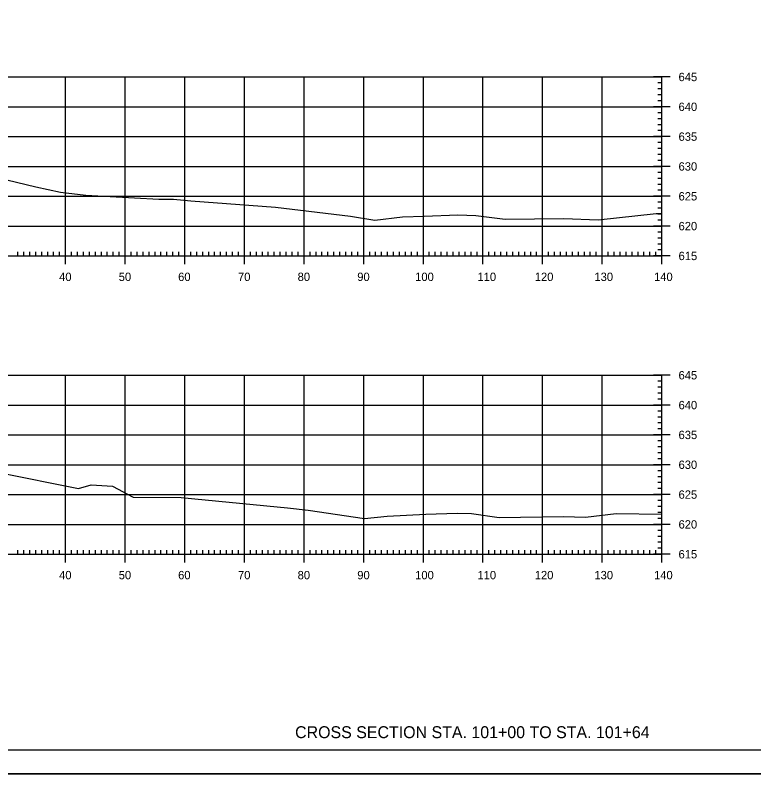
# Model space of a CAD drawing. Extents: x 1381471 to 1382703, y 370300 to 371487.
# Drawn here: x 1382168.2 to 1382292, y 370420.5 to 370547.6 of the extents above; entities that cross this region are included whole.
import ezdxf

# ---------------------------------------------------------------- set-up
doc = ezdxf.new("R2010")
doc.units = 0
doc.layers.add('Level 45', color=7, linetype='Continuous')

msp = doc.modelspace()

# ---------------------------------------------------------------- linework, layer by layer
at = {"layer": 'Level 45'}
for p, q in [((1381996.61, 370537.27), (1382276.61, 370537.27)), ((1382176.61, 370507.27), (1382176.61, 370537.27)), ((1382186.61, 370507.27), (1382186.61, 370537.27)), ((1382196.61, 370507.27), (1382196.61, 370537.27)), ((1382206.61, 370507.27), (1382206.61, 370537.27)), ((1382216.61, 370507.27), (1382216.61, 370537.27)), ((1382226.61, 370507.27), (1382226.61, 370537.27)), ((1382236.61, 370507.27), (1382236.61, 370537.27)), ((1382246.61, 370507.27), (1382246.61, 370537.27)), ((1382256.61, 370507.27), (1382256.61, 370537.27)), ((1382266.61, 370507.27), (1382266.61, 370537.27)), ((1382278.01, 370537.27), (1382275.21, 370537.27)), ((1382276.61, 370536.27), (1382275.91, 370536.27)), ((1382276.61, 370507.27), (1382276.61, 370537.27)), ((1382276.61, 370507.27), (1382276.61, 370537.27)), ((1382276.61, 370535.27), (1382275.91, 370535.27)), ((1382276.61, 370534.27), (1382275.91, 370534.27)), ((1382276.61, 370533.27), (1382275.91, 370533.27)), ((1381996.61, 370532.27), (1382276.61, 370532.27)), ((1382278.01, 370532.27), (1382275.21, 370532.27)), ((1382276.61, 370531.27), (1382275.91, 370531.27)), ((1382276.61, 370530.27), (1382275.91, 370530.27)), ((1382276.61, 370529.27), (1382275.91, 370529.27)), ((1381996.61, 370527.27), (1382276.61, 370527.27)), ((1382278.01, 370527.27), (1382275.21, 370527.27)), ((1382276.61, 370528.27), (1382275.91, 370528.27)), ((1382276.61, 370526.27), (1382275.91, 370526.27)), ((1382276.61, 370525.27), (1382275.91, 370525.27)), ((1382276.61, 370524.27), (1382275.91, 370524.27)), ((1381996.61, 370522.27), (1382276.61, 370522.27)), ((1382278.01, 370522.27), (1382275.21, 370522.27)), ((1382276.61, 370523.27), (1382275.91, 370523.27)), ((1382276.61, 370521.27), (1382275.91, 370521.27)), ((1382276.61, 370520.27), (1382275.91, 370520.27)), ((1382276.61, 370519.27), (1382275.91, 370519.27)), ((1381996.61, 370517.27), (1382276.61, 370517.27)), ((1382278.01, 370517.27), (1382275.21, 370517.27)), ((1382276.61, 370518.27), (1382275.91, 370518.27)), ((1382276.61, 370516.27), (1382275.91, 370516.27)), ((1382276.61, 370515.27), (1382275.91, 370515.27)), ((1382276.61, 370514.27), (1382275.91, 370514.27)), ((1381996.61, 370512.27), (1382276.61, 370512.27)), ((1382278.01, 370512.27), (1382275.21, 370512.27)), ((1382276.61, 370513.27), (1382275.91, 370513.27)), ((1382276.61, 370511.27), (1382275.91, 370511.27)), ((1382276.61, 370510.27), (1382275.91, 370510.27)), ((1382176.61, 370505.87), (1382176.61, 370508.67)), ((1382186.61, 370505.87), (1382186.61, 370508.67)), ((1382196.61, 370505.87), (1382196.61, 370508.67)), ((1382206.61, 370505.87), (1382206.61, 370508.67)), ((1382216.61, 370505.87), (1382216.61, 370508.67)), ((1382226.61, 370505.87), (1382226.61, 370508.67)), ((1382236.61, 370505.87), (1382236.61, 370508.67)), ((1382246.61, 370505.87), (1382246.61, 370508.67)), ((1382256.61, 370505.87), (1382256.61, 370508.67)), ((1382266.61, 370505.87), (1382266.61, 370508.67)), ((1382276.61, 370509.27), (1382275.91, 370509.27)), ((1382276.61, 370508.27), (1382275.91, 370508.27)), ((1382276.61, 370505.87), (1382276.61, 370508.67)), ((1381996.61, 370507.27), (1382276.61, 370507.27)), ((1381996.61, 370507.27), (1382276.61, 370507.27)), ((1382168.61, 370507.27), (1382168.61, 370507.97)), ((1382169.61, 370507.27), (1382169.61, 370507.97)), ((1382170.61, 370507.27), (1382170.61, 370507.97)), ((1382171.61, 370507.27), (1382171.61, 370507.97)), ((1382172.61, 370507.27), (1382172.61, 370507.97)), ((1382173.61, 370507.27), (1382173.61, 370507.97)), ((1382174.61, 370507.27), (1382174.61, 370507.97)), ((1382175.61, 370507.27), (1382175.61, 370507.97)), ((1382177.61, 370507.27), (1382177.61, 370507.97)), ((1382178.61, 370507.27), (1382178.61, 370507.97)), ((1382179.61, 370507.27), (1382179.61, 370507.97)), ((1382180.61, 370507.27), (1382180.61, 370507.97)), ((1382181.61, 370507.27), (1382181.61, 370507.97)), ((1382182.61, 370507.27), (1382182.61, 370507.97)), ((1382183.61, 370507.27), (1382183.61, 370507.97)), ((1382184.61, 370507.27), (1382184.61, 370507.97)), ((1382185.61, 370507.27), (1382185.61, 370507.97)), ((1382187.61, 370507.27), (1382187.61, 370507.97)), ((1382188.61, 370507.27), (1382188.61, 370507.97)), ((1382189.61, 370507.27), (1382189.61, 370507.97)), ((1382190.61, 370507.27), (1382190.61, 370507.97)), ((1382191.61, 370507.27), (1382191.61, 370507.97)), ((1382192.61, 370507.27), (1382192.61, 370507.97)), ((1382193.61, 370507.27), (1382193.61, 370507.97)), ((1382194.61, 370507.27), (1382194.61, 370507.97)), ((1382195.61, 370507.27), (1382195.61, 370507.97)), ((1382197.61, 370507.27), (1382197.61, 370507.97)), ((1382198.61, 370507.27), (1382198.61, 370507.97)), ((1382199.61, 370507.27), (1382199.61, 370507.97)), ((1382200.61, 370507.27), (1382200.61, 370507.97)), ((1382201.61, 370507.27), (1382201.61, 370507.97)), ((1382202.61, 370507.27), (1382202.61, 370507.97)), ((1382203.61, 370507.27), (1382203.61, 370507.97)), ((1382204.61, 370507.27), (1382204.61, 370507.97)), ((1382205.61, 370507.27), (1382205.61, 370507.97)), ((1382207.61, 370507.27), (1382207.61, 370507.97)), ((1382208.61, 370507.27), (1382208.61, 370507.97)), ((1382209.61, 370507.27), (1382209.61, 370507.97)), ((1382210.61, 370507.27), (1382210.61, 370507.97)), ((1382211.61, 370507.27), (1382211.61, 370507.97)), ((1382212.61, 370507.27), (1382212.61, 370507.97)), ((1382213.61, 370507.27), (1382213.61, 370507.97)), ((1382214.61, 370507.27), (1382214.61, 370507.97)), ((1382215.61, 370507.27), (1382215.61, 370507.97)), ((1382217.61, 370507.27), (1382217.61, 370507.97)), ((1382218.61, 370507.27), (1382218.61, 370507.97)), ((1382219.61, 370507.27), (1382219.61, 370507.97)), ((1382220.61, 370507.27), (1382220.61, 370507.97)), ((1382221.61, 370507.27), (1382221.61, 370507.97)), ((1382222.61, 370507.27), (1382222.61, 370507.97)), ((1382223.61, 370507.27), (1382223.61, 370507.97)), ((1382224.61, 370507.27), (1382224.61, 370507.97)), ((1382225.61, 370507.27), (1382225.61, 370507.97)), ((1382227.61, 370507.27), (1382227.61, 370507.97)), ((1382228.61, 370507.27), (1382228.61, 370507.97)), ((1382229.61, 370507.27), (1382229.61, 370507.97)), ((1382230.61, 370507.27), (1382230.61, 370507.97)), ((1382231.61, 370507.27), (1382231.61, 370507.97)), ((1382232.61, 370507.27), (1382232.61, 370507.97)), ((1382233.61, 370507.27), (1382233.61, 370507.97)), ((1382234.61, 370507.27), (1382234.61, 370507.97)), ((1382235.61, 370507.27), (1382235.61, 370507.97)), ((1382237.61, 370507.27), (1382237.61, 370507.97)), ((1382238.61, 370507.27), (1382238.61, 370507.97)), ((1382239.61, 370507.27), (1382239.61, 370507.97)), ((1382240.61, 370507.27), (1382240.61, 370507.97)), ((1382241.61, 370507.27), (1382241.61, 370507.97)), ((1382242.61, 370507.27), (1382242.61, 370507.97)), ((1382243.61, 370507.27), (1382243.61, 370507.97)), ((1382244.61, 370507.27), (1382244.61, 370507.97)), ((1382245.61, 370507.27), (1382245.61, 370507.97)), ((1382247.61, 370507.27), (1382247.61, 370507.97)), ((1382248.61, 370507.27), (1382248.61, 370507.97)), ((1382249.61, 370507.27), (1382249.61, 370507.97)), ((1382250.61, 370507.27), (1382250.61, 370507.97)), ((1382251.61, 370507.27), (1382251.61, 370507.97)), ((1382252.61, 370507.27), (1382252.61, 370507.97)), ((1382253.61, 370507.27), (1382253.61, 370507.97)), ((1382254.61, 370507.27), (1382254.61, 370507.97)), ((1382255.61, 370507.27), (1382255.61, 370507.97)), ((1382257.61, 370507.27), (1382257.61, 370507.97)), ((1382258.61, 370507.27), (1382258.61, 370507.97)), ((1382259.61, 370507.27), (1382259.61, 370507.97)), ((1382260.61, 370507.27), (1382260.61, 370507.97)), ((1382261.61, 370507.27), (1382261.61, 370507.97)), ((1382262.61, 370507.27), (1382262.61, 370507.97)), ((1382263.61, 370507.27), (1382263.61, 370507.97)), ((1382264.61, 370507.27), (1382264.61, 370507.97)), ((1382265.61, 370507.27), (1382265.61, 370507.97)), ((1382267.61, 370507.27), (1382267.61, 370507.97)), ((1382268.61, 370507.27), (1382268.61, 370507.97)), ((1382269.61, 370507.27), (1382269.61, 370507.97)), ((1382270.61, 370507.27), (1382270.61, 370507.97)), ((1382271.61, 370507.27), (1382271.61, 370507.97)), ((1382272.61, 370507.27), (1382272.61, 370507.97)), ((1382273.61, 370507.27), (1382273.61, 370507.97)), ((1382274.61, 370507.27), (1382274.61, 370507.97)), ((1382278.01, 370507.27), (1382275.21, 370507.27)), ((1382275.61, 370507.27), (1382275.61, 370507.97)), ((1381996.61, 370487.27), (1382276.61, 370487.27)), ((1382176.61, 370457.27), (1382176.61, 370487.27)), ((1382186.61, 370457.27), (1382186.61, 370487.27)), ((1382196.61, 370457.27), (1382196.61, 370487.27)), ((1382206.61, 370457.27), (1382206.61, 370487.27)), ((1382216.61, 370457.27), (1382216.61, 370487.27)), ((1382226.61, 370457.27), (1382226.61, 370487.27)), ((1382236.61, 370457.27), (1382236.61, 370487.27)), ((1382246.61, 370457.27), (1382246.61, 370487.27)), ((1382256.61, 370457.27), (1382256.61, 370487.27)), ((1382266.61, 370457.27), (1382266.61, 370487.27)), ((1382278.01, 370487.27), (1382275.21, 370487.27)), ((1382276.61, 370457.27), (1382276.61, 370487.27)), ((1382276.61, 370457.27), (1382276.61, 370487.27)), ((1382276.61, 370486.27), (1382275.91, 370486.27)), ((1382276.61, 370485.27), (1382275.91, 370485.27)), ((1382276.61, 370484.27), (1382275.91, 370484.27)), ((1382276.61, 370483.27), (1382275.91, 370483.27)), ((1381996.61, 370482.27), (1382276.61, 370482.27)), ((1382278.01, 370482.27), (1382275.21, 370482.27)), ((1382276.61, 370481.27), (1382275.91, 370481.27)), ((1382276.61, 370480.27), (1382275.91, 370480.27)), ((1382276.61, 370479.27), (1382275.91, 370479.27)), ((1382276.61, 370478.27), (1382275.91, 370478.27)), ((1381996.61, 370477.27), (1382276.61, 370477.27)), ((1382278.01, 370477.27), (1382275.21, 370477.27)), ((1382276.61, 370476.27), (1382275.91, 370476.27)), ((1382276.61, 370475.27), (1382275.91, 370475.27)), ((1382276.61, 370474.27), (1382275.91, 370474.27)), ((1382276.61, 370473.27), (1382275.91, 370473.27)), ((1381996.61, 370472.27), (1382276.61, 370472.27)), ((1382278.01, 370472.27), (1382275.21, 370472.27)), ((1382276.61, 370471.27), (1382275.91, 370471.27)), ((1382276.61, 370470.27), (1382275.91, 370470.27)), ((1382276.61, 370469.27), (1382275.91, 370469.27)), ((1382276.61, 370468.27), (1382275.91, 370468.27)), ((1381996.61, 370467.27), (1382276.61, 370467.27)), ((1382278.01, 370467.27), (1382275.21, 370467.27)), ((1382276.61, 370466.27), (1382275.91, 370466.27)), ((1382276.61, 370465.27), (1382275.91, 370465.27)), ((1382276.61, 370464.27), (1382275.91, 370464.27)), ((1382276.61, 370463.27), (1382275.91, 370463.27)), ((1381996.61, 370462.27), (1382276.61, 370462.27)), ((1382278.01, 370462.27), (1382275.21, 370462.27)), ((1382276.61, 370461.27), (1382275.91, 370461.27)), ((1382276.61, 370460.27), (1382275.91, 370460.27)), ((1382176.61, 370455.87), (1382176.61, 370458.67)), ((1382186.61, 370455.87), (1382186.61, 370458.67)), ((1382196.61, 370455.87), (1382196.61, 370458.67)), ((1382206.61, 370455.87), (1382206.61, 370458.67)), ((1382216.61, 370455.87), (1382216.61, 370458.67)), ((1382226.61, 370455.87), (1382226.61, 370458.67)), ((1382236.61, 370455.87), (1382236.61, 370458.67)), ((1382246.61, 370455.87), (1382246.61, 370458.67)), ((1382256.61, 370455.87), (1382256.61, 370458.67)), ((1382266.61, 370455.87), (1382266.61, 370458.67)), ((1382276.61, 370459.27), (1382275.91, 370459.27)), ((1382276.61, 370455.87), (1382276.61, 370458.67)), ((1382168.61, 370457.27), (1382168.61, 370457.97)), ((1382169.61, 370457.27), (1382169.61, 370457.97)), ((1382170.61, 370457.27), (1382170.61, 370457.97)), ((1382171.61, 370457.27), (1382171.61, 370457.97)), ((1382172.61, 370457.27), (1382172.61, 370457.97)), ((1382173.61, 370457.27), (1382173.61, 370457.97)), ((1382174.61, 370457.27), (1382174.61, 370457.97)), ((1382175.61, 370457.27), (1382175.61, 370457.97)), ((1382177.61, 370457.27), (1382177.61, 370457.97)), ((1382178.61, 370457.27), (1382178.61, 370457.97)), ((1382179.61, 370457.27), (1382179.61, 370457.97)), ((1382180.61, 370457.27), (1382180.61, 370457.97)), ((1382181.61, 370457.27), (1382181.61, 370457.97)), ((1382182.61, 370457.27), (1382182.61, 370457.97)), ((1382183.61, 370457.27), (1382183.61, 370457.97)), ((1382184.61, 370457.27), (1382184.61, 370457.97)), ((1382185.61, 370457.27), (1382185.61, 370457.97)), ((1382187.61, 370457.27), (1382187.61, 370457.97)), ((1382188.61, 370457.27), (1382188.61, 370457.97)), ((1382189.61, 370457.27), (1382189.61, 370457.97)), ((1382190.61, 370457.27), (1382190.61, 370457.97)), ((1382191.61, 370457.27), (1382191.61, 370457.97)), ((1382192.61, 370457.27), (1382192.61, 370457.97)), ((1382193.61, 370457.27), (1382193.61, 370457.97)), ((1382194.61, 370457.27), (1382194.61, 370457.97)), ((1382195.61, 370457.27), (1382195.61, 370457.97)), ((1382197.61, 370457.27), (1382197.61, 370457.97)), ((1382198.61, 370457.27), (1382198.61, 370457.97)), ((1382199.61, 370457.27), (1382199.61, 370457.97)), ((1382200.61, 370457.27), (1382200.61, 370457.97)), ((1382201.61, 370457.27), (1382201.61, 370457.97)), ((1382202.61, 370457.27), (1382202.61, 370457.97)), ((1382203.61, 370457.27), (1382203.61, 370457.97)), ((1382204.61, 370457.27), (1382204.61, 370457.97)), ((1382205.61, 370457.27), (1382205.61, 370457.97)), ((1382207.61, 370457.27), (1382207.61, 370457.97)), ((1382208.61, 370457.27), (1382208.61, 370457.97)), ((1382209.61, 370457.27), (1382209.61, 370457.97)), ((1382210.61, 370457.27), (1382210.61, 370457.97)), ((1382211.61, 370457.27), (1382211.61, 370457.97)), ((1382212.61, 370457.27), (1382212.61, 370457.97)), ((1382213.61, 370457.27), (1382213.61, 370457.97)), ((1382214.61, 370457.27), (1382214.61, 370457.97)), ((1382215.61, 370457.27), (1382215.61, 370457.97)), ((1382217.61, 370457.27), (1382217.61, 370457.97)), ((1382218.61, 370457.27), (1382218.61, 370457.97)), ((1382219.61, 370457.27), (1382219.61, 370457.97)), ((1382220.61, 370457.27), (1382220.61, 370457.97)), ((1382221.61, 370457.27), (1382221.61, 370457.97)), ((1382222.61, 370457.27), (1382222.61, 370457.97)), ((1382223.61, 370457.27), (1382223.61, 370457.97)), ((1382224.61, 370457.27), (1382224.61, 370457.97)), ((1382225.61, 370457.27), (1382225.61, 370457.97)), ((1382227.61, 370457.27), (1382227.61, 370457.97)), ((1382228.61, 370457.27), (1382228.61, 370457.97)), ((1382229.61, 370457.27), (1382229.61, 370457.97)), ((1382230.61, 370457.27), (1382230.61, 370457.97)), ((1382231.61, 370457.27), (1382231.61, 370457.97)), ((1382232.61, 370457.27), (1382232.61, 370457.97)), ((1382233.61, 370457.27), (1382233.61, 370457.97)), ((1382234.61, 370457.27), (1382234.61, 370457.97)), ((1382235.61, 370457.27), (1382235.61, 370457.97)), ((1382237.61, 370457.27), (1382237.61, 370457.97)), ((1382238.61, 370457.27), (1382238.61, 370457.97)), ((1382239.61, 370457.27), (1382239.61, 370457.97)), ((1382240.61, 370457.27), (1382240.61, 370457.97)), ((1382241.61, 370457.27), (1382241.61, 370457.97)), ((1382242.61, 370457.27), (1382242.61, 370457.97)), ((1382243.61, 370457.27), (1382243.61, 370457.97)), ((1382244.61, 370457.27), (1382244.61, 370457.97)), ((1382245.61, 370457.27), (1382245.61, 370457.97)), ((1382247.61, 370457.27), (1382247.61, 370457.97)), ((1382248.61, 370457.27), (1382248.61, 370457.97)), ((1382249.61, 370457.27), (1382249.61, 370457.97)), ((1382250.61, 370457.27), (1382250.61, 370457.97)), ((1382251.61, 370457.27), (1382251.61, 370457.97)), ((1382252.61, 370457.27), (1382252.61, 370457.97)), ((1382253.61, 370457.27), (1382253.61, 370457.97)), ((1382254.61, 370457.27), (1382254.61, 370457.97)), ((1382255.61, 370457.27), (1382255.61, 370457.97)), ((1382257.61, 370457.27), (1382257.61, 370457.97)), ((1382258.61, 370457.27), (1382258.61, 370457.97)), ((1382259.61, 370457.27), (1382259.61, 370457.97)), ((1382260.61, 370457.27), (1382260.61, 370457.97)), ((1382261.61, 370457.27), (1382261.61, 370457.97)), ((1382262.61, 370457.27), (1382262.61, 370457.97)), ((1382263.61, 370457.27), (1382263.61, 370457.97)), ((1382264.61, 370457.27), (1382264.61, 370457.97)), ((1382265.61, 370457.27), (1382265.61, 370457.97)), ((1382267.61, 370457.27), (1382267.61, 370457.97)), ((1382268.61, 370457.27), (1382268.61, 370457.97)), ((1382269.61, 370457.27), (1382269.61, 370457.97)), ((1382270.61, 370457.27), (1382270.61, 370457.97)), ((1382271.61, 370457.27), (1382271.61, 370457.97)), ((1382272.61, 370457.27), (1382272.61, 370457.97)), ((1382273.61, 370457.27), (1382273.61, 370457.97)), ((1382274.61, 370457.27), (1382274.61, 370457.97)), ((1382275.61, 370457.27), (1382275.61, 370457.97)), ((1382276.61, 370458.27), (1382275.91, 370458.27)), ((1381996.61, 370457.27), (1382276.61, 370457.27)), ((1381996.61, 370457.27), (1382276.61, 370457.27)), ((1382278.01, 370457.27), (1382275.21, 370457.27)), ((1382294.79, 370424.44), (1381978.61, 370424.44)), ((1381966.21, 370420.47), (1382299.55, 370420.47))]:
    msp.add_line(p, q, dxfattribs=at)
for points in [[(1381966.21, 370633.8), (1382299.55, 370633.8), (1382299.55, 370420.46), (1381966.21, 370420.46)], [(1382212.53, 370629.9), (1382232.15, 370629.9), (1382232.15, 370620.02), (1382248.27, 370620.02), (1382271.46, 370620.02), (1382271.46, 370595.69), (1382294.79, 370595.69), (1382294.79, 370424.44), (1381978.61, 370424.44), (1381978.61, 370629.9)]]:
    msp.add_lwpolyline(points, close=True, dxfattribs=at)
for points in [[(1382163.45, 370520.8), (1382171.63, 370518.87), (1382175.75, 370517.95), (1382180.03, 370517.46), (1382192.24, 370516.79), (1382194.73, 370516.78), (1382197.6, 370516.5), (1382211.84, 370515.47), (1382224.39, 370513.92), (1382228.47, 370513.24), (1382233.09, 370513.82), (1382236.76, 370513.96), (1382242.39, 370514.18), (1382245.4, 370514.07), (1382250.33, 370513.42), (1382260.16, 370513.56), (1382265.93, 370513.35), (1382275.65, 370514.38), (1382276.61, 370514.38)], [(1382165.34, 370470.97), (1382178.79, 370468.31), (1382180.91, 370468.89), (1382184.49, 370468.67), (1382187.96, 370466.83), (1382196, 370466.78), (1382212.07, 370465.19), (1382213.84, 370465.07), (1382217.31, 370464.67), (1382226.75, 370463.28), (1382230.52, 370463.67), (1382237.04, 370463.96), (1382242.28, 370464.18), (1382244.66, 370464.1), (1382249.35, 370463.42), (1382260.09, 370463.59), (1382263.82, 370463.46), (1382268.95, 370464.07), (1382276.61, 370464.01)]]:
    msp.add_lwpolyline(points, dxfattribs=at)

# ---------------------------------------------------------------- texts
for s, height, p in [('645', 1.4, (1382279.41, 370536.57)), ('640', 1.4, (1382279.41, 370531.57)), ('635', 1.4, (1382279.41, 370526.57)), ('630', 1.4, (1382279.41, 370521.57)), ('625', 1.4, (1382279.41, 370516.57)), ('620', 1.4, (1382279.41, 370511.57)), ('615', 1.4, (1382279.41, 370506.57)), ('40', 1.4, (1382175.53, 370503.07)), ('50', 1.4, (1382185.53, 370503.07)), ('60', 1.4, (1382195.49, 370503.07)), ('70', 1.4, (1382205.53, 370503.07)), ('80', 1.4, (1382215.53, 370503.07)), ('90', 1.4, (1382225.53, 370503.07)), ('100', 1.4, (1382235.24, 370503.07)), ('110', 1.4, (1382245.69, 370503.07)), ('120', 1.4, (1382255.3, 370503.07)), ('130', 1.4, (1382265.3, 370503.07)), ('140', 1.4, (1382275.3, 370503.07)), ('645', 1.4, (1382279.41, 370486.57)), ('640', 1.4, (1382279.41, 370481.57)), ('635', 1.4, (1382279.41, 370476.57)), ('630', 1.4, (1382279.41, 370471.57)), ('625', 1.4, (1382279.41, 370466.57)), ('620', 1.4, (1382279.41, 370461.57)), ('615', 1.4, (1382279.41, 370456.57)), ('40', 1.4, (1382175.53, 370453.07)), ('50', 1.4, (1382185.53, 370453.07)), ('60', 1.4, (1382195.49, 370453.07)), ('70', 1.4, (1382205.53, 370453.07)), ('80', 1.4, (1382215.53, 370453.07)), ('90', 1.4, (1382225.53, 370453.07)), ('100', 1.4, (1382235.24, 370453.07)), ('110', 1.4, (1382245.69, 370453.07)), ('120', 1.4, (1382255.3, 370453.07)), ('130', 1.4, (1382265.3, 370453.07)), ('140', 1.4, (1382275.3, 370453.07)), ('CROSS SECTION STA. 101+00 TO STA. 101+64', 2, (1382215.1, 370426.44))]:
    msp.add_text(s, height=height, dxfattribs=at).set_placement(p)

doc.saveas('drawing.dxf')
